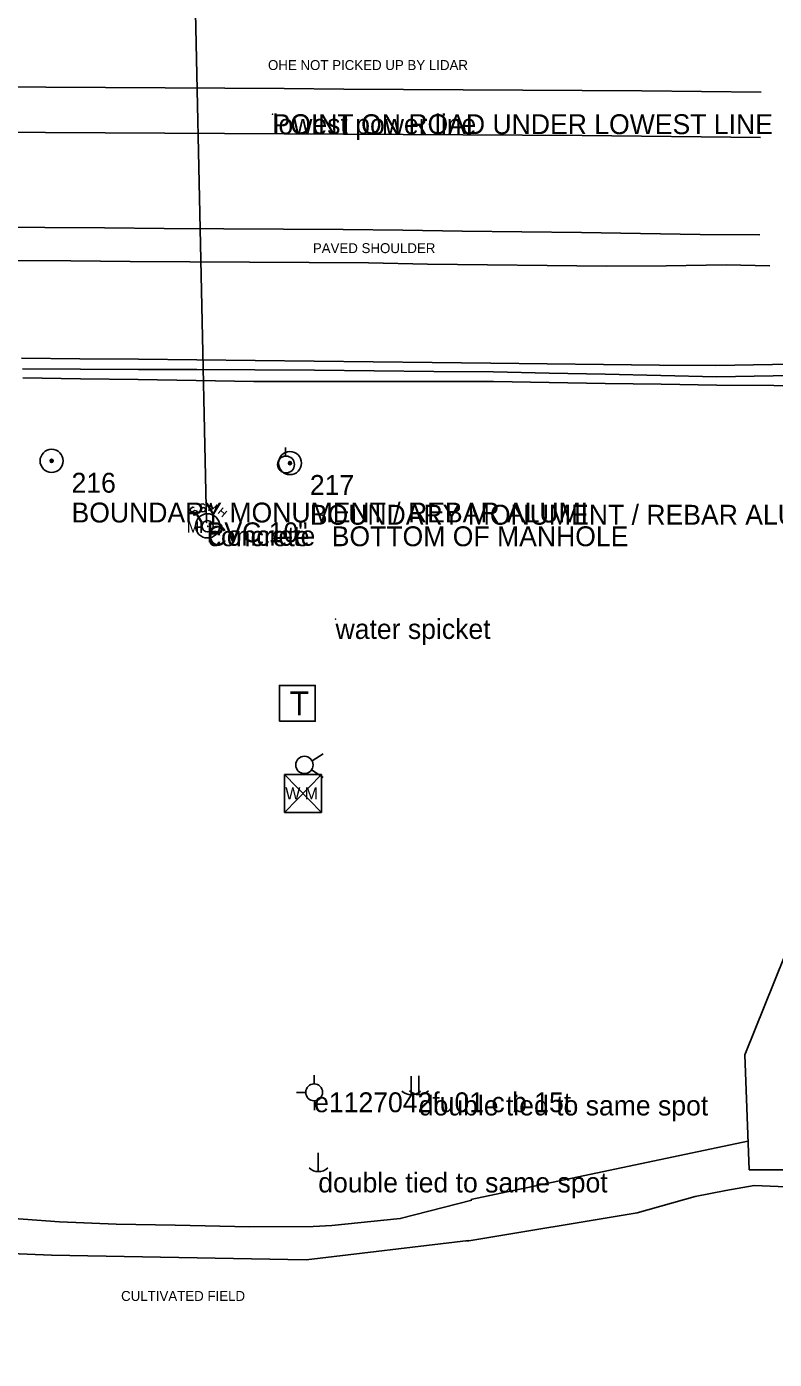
# Model space of a CAD drawing. Extents: x 1802180 to 1804859, y 572524 to 575172.
# Drawn here: x 1804394.4 to 1804582.6, y 573491.7 to 573826.9 of the extents above; entities that cross this region are included whole.
import ezdxf

# ---------------------------------------------------------------- set-up
doc = ezdxf.new("R2010")
doc.units = 0
for name, color, linetype in [('EX_EDGE_PAVEMENT', 7, 'Continuous'), ('EX_SHOULDER', 7, 'Continuous'), ('S_DITCHLINE', 7, 'Continuous'), ('S_ELECTRIC_UTILITIES_ANNOT', 7, 'Continuous'), ('S_IRON_PIN', 7, 'Continuous'), ('S_IRON_PIN_ANNOT', 7, 'Continuous'), ('S_MANHOLE', 7, 'Continuous'), ('S_MANHOLE_ANNOT', 7, 'Continuous'), ('S_MISC_BOUNDARY', 7, 'Continuous'), ('S_MISC_BOUNDARY_ANNOT', 7, 'Continuous'), ('S_MSC_PT_SYM', 7, 'Continuous'), ('S_PARKING', 7, 'Continuous'), ('S_PAVEMENT_CROWN', 7, 'Continuous'), ('S_SANITARY_SEWER', 7, 'Continuous'), ('S_SANITARY_SEWER_ANNOT', 7, 'Continuous'), ('S_SHOULDER_ANNOT', 7, 'Continuous'), ('S_SURVEY_TEXT', 7, 'Continuous'), ('S_SURVEY_TEXT_ANNOT', 7, 'Continuous'), ('S_TELEPHONE_UTILITIES', 7, 'Continuous'), ('S_TRAILS', 7, 'Continuous'), ('S_UTILITY_POLE', 7, 'Continuous'), ('S_UTILITY_POLE_ANNOT', 7, 'Continuous'), ('S_UTL_PT_SYM', 7, 'Continuous'), ('S_WATER_UTILITIES', 7, 'Continuous')]:
    doc.layers.add(name, color=color, linetype=linetype)

msp = doc.modelspace()

# ---------------------------------------------------------------- linework, layer by layer
at = {"layer": 'EX_EDGE_PAVEMENT'}
msp.add_lwpolyline([(1804578.95, 573774.58), (1804563.95, 573774.68), (1804548.95, 573774.89), (1804534.07, 573775.15), (1804519.07, 573775.33), (1804504.07, 573775.48), (1804489.08, 573775.71), (1804474.08, 573775.95), (1804459.08, 573776.02), (1804444.08, 573776.08), (1804429.05, 573776.18), (1804414.05, 573776.29), (1804399.05, 573776.4), (1804384.14, 573776.49)], dxfattribs=at)
at = {"layer": 'EX_SHOULDER'}
msp.add_lwpolyline([(1804270.56, 573769.08), (1804285.47, 573768.95), (1804300.47, 573768.69), (1804315.5, 573768.52), (1804330.52, 573768.41), (1804345.52, 573768.3), (1804360.53, 573768.22), (1804375.55, 573768.19), (1804390.52, 573768.1), (1804405.52, 573768), (1804420.51, 573767.89), (1804435.52, 573767.78), (1804450.52, 573767.69), (1804465.55, 573767.65), (1804480.52, 573767.56), (1804495.37, 573767.21), (1804510.47, 573767.06), (1804525.47, 573766.88), (1804540.38, 573766.7), (1804555.38, 573766.8), (1804570.51, 573767.04), (1804581.48, 573766.76)], dxfattribs=at)
at = {"layer": 'S_DITCHLINE'}
for points in [[(1804393.16, 573743.54), (1804407.86, 573743.4), (1804422.57, 573743.25), (1804437.28, 573743.1), (1804451.98, 573742.96), (1804466.81, 573742.8), (1804481.64, 573742.64), (1804496.47, 573742.48), (1804511.3, 573742.32), (1804525.45, 573742.15), (1804539.61, 573741.99), (1804553.76, 573741.82), (1804567.92, 573741.66), (1804582.19, 573741.99), (1804596.45, 573742.33)], [(1804393.35, 573740.82), (1804407.98, 573740.78), (1804422.6, 573740.73), (1804437.23, 573740.69), (1804451.85, 573740.65), (1804466.88, 573740.51), (1804481.9, 573740.37), (1804496.93, 573740.23), (1804511.95, 573740.1), (1804525.98, 573739.79), (1804540.02, 573739.49), (1804554.05, 573739.18), (1804568.08, 573738.88), (1804582.3, 573739.13), (1804596.52, 573739.38)], [(1804393.44, 573738.62), (1804407.99, 573738.38), (1804422.54, 573738.15), (1804437.08, 573737.91), (1804451.63, 573737.68), (1804466.7, 573737.67), (1804481.77, 573737.66), (1804496.84, 573737.65), (1804511.91, 573737.64), (1804525.98, 573737.41), (1804540.05, 573737.19), (1804554.11, 573736.97), (1804568.18, 573736.75), (1804582.53, 573736.68), (1804596.88, 573736.62)]]:
    msp.add_lwpolyline(points, dxfattribs=at)
at = {"layer": 'S_IRON_PIN'}
for centre, radius in [((1804400.73, 573717.71), 2.91), ((1804400.73, 573717.71), 0.411), ((1804400.73, 573717.71), 0.262), ((1804400.73, 573717.71), 0.212), ((1804400.73, 573717.71), 0.145), ((1804400.73, 573717.71), 0.0822), ((1804400.73, 573717.71), 0.0581), ((1804460.72, 573717.15), 2.91), ((1804460.72, 573717.15), 0.411), ((1804460.72, 573717.15), 0.262), ((1804460.72, 573717.15), 0.212), ((1804460.72, 573717.15), 0.145), ((1804460.72, 573717.15), 0.0822), ((1804460.72, 573717.15), 0.0581)]:
    msp.add_circle(centre, radius, dxfattribs=at)
at = {"layer": 'S_MANHOLE'}
for p, q in [((1804436.82, 573701.04), (1804438.4, 573701.04)), ((1804438.4, 573699.63), (1804438.4, 573702.47))]:
    msp.add_line(p, q, dxfattribs=at)
msp.add_circle((1804439.99, 573701.25), 1.42, dxfattribs=at)
at = {"layer": 'S_MISC_BOUNDARY'}
for points in [[(1804505.21, 573521.43), (1804548.12, 573528.55), (1804562.67, 573532.64), (1804570.46, 573534.2), (1804577.56, 573535.38), (1804635.95, 573532.96), (1804699.73, 573530.94), (1804713.49, 573529.95), (1804733.85, 573526.62), (1804745.57, 573524.69), (1804765.3, 573523.78), (1804783.44, 573521.61), (1804800.81, 573520.18), (1804809.98, 573519.87), (1804816.92, 573516.85), (1804820.25, 573513.61), (1804821.85, 573510.93)], [(1804339.86, 573491.68), (1804339.25, 573520.41), (1804400.7, 573517.93), (1804464.79, 573516.71), (1804505.61, 573521.55)]]:
    msp.add_lwpolyline(points, dxfattribs=at)
at = {"layer": 'S_MSC_PT_SYM'}
for points in [[(1804456.33, 573804.9), (1804456.33, 573804.95), (1804456.33, 573804.9), (1804456.28, 573804.9), (1804456.33, 573804.9), (1804456.33, 573804.85), (1804456.33, 573804.9), (1804456.38, 573804.9)], [(1804472.19, 573677.91), (1804472.19, 573677.96), (1804472.19, 573677.91), (1804472.14, 573677.91), (1804472.19, 573677.91), (1804472.19, 573677.86), (1804472.19, 573677.91), (1804472.24, 573677.91)]]:
    msp.add_lwpolyline(points, dxfattribs=at)
at = {"layer": 'S_PARKING'}
msp.add_lwpolyline([(1804786.88, 573526.83), (1804786.88, 573526.83), (1804744.65, 573531.49), (1804677.97, 573539.39), (1804576.31, 573539.38), (1804575.23, 573568.33), (1804600.03, 573629.91), (1804655.49, 573715.42)], dxfattribs=at)
at = {"layer": 'S_PAVEMENT_CROWN'}
for points in [[(1804579.29, 573810.48), (1804564.29, 573810.62), (1804549.29, 573810.76), (1804534.29, 573810.88), (1804519.29, 573810.97), (1804504.29, 573811.06), (1804489.29, 573811.15), (1804474.29, 573811.25), (1804459.29, 573811.34), (1804444.29, 573811.43), (1804429.29, 573811.52), (1804414.29, 573811.62), (1804399.29, 573811.73), (1804384.29, 573811.82)], [(1804384.24, 573800.44), (1804399.21, 573800.35), (1804414.21, 573800.24), (1804429.21, 573800.13), (1804444.22, 573800.04), (1804459.22, 573799.97), (1804474.22, 573799.9), (1804489.22, 573799.81), (1804504.22, 573799.71), (1804519.22, 573799.61), (1804534.22, 573799.52), (1804549.18, 573799.38), (1804564.18, 573799.22), (1804579.18, 573799.02)]]:
    msp.add_lwpolyline(points, dxfattribs=at)
at = {"layer": 'S_SANITARY_SEWER'}
for p, q in [((1804439.74, 573702.23), (1804435.17, 573908.88)), ((1804435.64, 573705.67), (1804435.56, 573705.28)), ((1804435.56, 573705.28), (1804435.76, 573705.01)), ((1804436.18, 573706.05), (1804435.64, 573705.67)), ((1804435.76, 573705.01), (1804436.18, 573704.89)), ((1804436.61, 573705.98), (1804436.18, 573706.05)), ((1804436.18, 573704.89), (1804436.73, 573705.24)), ((1804436.73, 573705.24), (1804437.19, 573705.16)), ((1804437.27, 573704.46), (1804436.73, 573704.08)), ((1804437.19, 573705.16), (1804437.35, 573704.89)), ((1804437.35, 573704.89), (1804437.27, 573704.46)), ((1804442.62, 573704.43), (1804443.86, 573705.9)), ((1804443.28, 573705.2), (1804444.24, 573704.39)), ((1804444.83, 573705.08), (1804443.59, 573703.61)), ((1804436.73, 573704.08), (1804436.34, 573704.15))]:
    msp.add_line(p, q, dxfattribs=at)
for points in [[(1804439.28, 573706.6), (1804438.94, 573706.87), (1804438.28, 573706.79), (1804438.04, 573706.44), (1804438.08, 573706.13), (1804438.43, 573705.82), (1804439.05, 573705.94), (1804439.44, 573705.63), (1804439.48, 573705.32), (1804439.21, 573704.93), (1804438.59, 573704.85), (1804438.24, 573705.12)], [(1804441.73, 573704.74), (1804442.27, 573706.6), (1804441.22, 573705.59), (1804440.83, 573707.02), (1804440.29, 573705.16)]]:
    msp.add_lwpolyline(points, dxfattribs=at)
msp.add_circle((1804439.97, 573701.36), 3.05, dxfattribs=at)
at = {"layer": 'S_SURVEY_TEXT'}
msp.add_line((1804455.18, 573818.53), (1804455.18, 573818.53), dxfattribs=at)
at = {"layer": 'S_TELEPHONE_UTILITIES'}
msp.add_lwpolyline([(1804458.06, 573652.21), (1804458.06, 573661.21), (1804467.06, 573661.21), (1804467.06, 573652.21)], close=True, dxfattribs=at)
at = {"layer": 'S_TRAILS'}
msp.add_line((1804506.23, 573531.88), (1804575.96, 573546.6), dxfattribs=at)
msp.add_lwpolyline([(1804237.78, 573515.53), (1804237.78, 573515.53), (1804256.03, 573517.74), (1804309, 573528.42), (1804314.65, 573530.34), (1804320.9, 573530.65), (1804330.17, 573530.55), (1804346.23, 573530.21), (1804362.73, 573528.81), (1804384.35, 573527.65), (1804402.68, 573526.31), (1804416.97, 573525.69), (1804431.84, 573525.41), (1804450.6, 573524.99), (1804466.55, 573525.14), (1804471.29, 573525.33), (1804488.47, 573527.11), (1804506.5, 573531.75)], dxfattribs=at)
at = {"layer": 'S_UTILITY_POLE'}
for p, q in [((1804459.6, 573718.93), (1804459.6, 573721.03)), ((1804466.8, 573560.96), (1804466.8, 573563.21)), ((1804491.19, 573562.95), (1804491.19, 573558.22)), ((1804493.12, 573562.99), (1804493.12, 573558.26)), ((1804464.71, 573558.83), (1804462.38, 573558.83)), ((1804466.88, 573554.41), (1804466.88, 573556.74)), ((1804467.81, 573543.61), (1804467.81, 573538.89))]:
    msp.add_line(p, q, dxfattribs=at)
for centre in [(1804459.72, 573716.79), (1804466.8, 573558.85)]:
    msp.add_circle(centre, 2.13, dxfattribs=at)
for centre in [(1804491.25, 573561.64), (1804493.19, 573561.68), (1804467.88, 573542.31)]:
    msp.add_arc(centre, 3.41, 226.3972, 313.6028, dxfattribs=at)
at = {"layer": 'S_UTL_PT_SYM'}
for points in [[(1804456.33, 573804.9), (1804456.33, 573804.95), (1804456.33, 573804.9), (1804456.28, 573804.9), (1804456.33, 573804.9), (1804456.33, 573804.85), (1804456.33, 573804.9), (1804456.38, 573804.9)], [(1804439.74, 573702.23), (1804439.74, 573702.28), (1804439.74, 573702.23), (1804439.69, 573702.23), (1804439.74, 573702.23), (1804439.74, 573702.18), (1804439.74, 573702.23), (1804439.79, 573702.23)], [(1804440.01, 573701.24), (1804440.01, 573701.29), (1804440.01, 573701.24), (1804439.96, 573701.24), (1804440.01, 573701.24), (1804440.01, 573701.19), (1804440.01, 573701.24), (1804440.06, 573701.24)]]:
    msp.add_lwpolyline(points, dxfattribs=at)
at = {"layer": 'S_WATER_UTILITIES'}
for p, q in [((1804466.26, 573642.26), (1804469.08, 573643.99)), ((1804459.33, 573638.77), (1804468.67, 573638.77)), ((1804459.33, 573638.77), (1804459.33, 573629.28)), ((1804459.33, 573638.77), (1804468.67, 573629.28)), ((1804468.67, 573638.77), (1804459.33, 573629.28)), ((1804466.14, 573639.95), (1804469.05, 573638.03)), ((1804468.67, 573638.77), (1804468.67, 573629.28)), ((1804459.33, 573629.28), (1804468.67, 573629.28))]:
    msp.add_line(p, q, dxfattribs=at)
msp.add_circle((1804464.36, 573641.21), 2.18, dxfattribs=at)

# ---------------------------------------------------------------- texts
at = {"layer": 'S_ELECTRIC_UTILITIES_ANNOT'}
msp.add_text('lowest power line ', height=5, dxfattribs=at).set_placement((1804456.33, 573799.9))
at = {"layer": 'S_IRON_PIN_ANNOT'}
for s, p in [('216', (1804405.73, 573709.71)), ('217', (1804465.72, 573709.15)), ('BOUNDARY MONUMENT / REBAR ALUMI ', (1804405.73, 573702.21)), ('BOUNDARY MONUMENT / REBAR ALUMI ', (1804465.72, 573701.65))]:
    msp.add_text(s, height=5, dxfattribs=at).set_placement(p)
at = {"layer": 'S_MANHOLE'}
msp.add_text('M', height=2.82, dxfattribs=at).set_placement((1804434.74, 573699.67))
at = {"layer": 'S_MANHOLE_ANNOT'}
msp.add_text('concrete   BOTTOM OF MANHOLE', height=5, dxfattribs=at).set_placement((1804440.01, 573696.24))
at = {"layer": 'S_MISC_BOUNDARY_ANNOT'}
msp.add_text('CULTIVATED FIELD', height=2.5, dxfattribs=at).set_placement((1804418.21, 573506.38))
at = {"layer": 'S_SANITARY_SEWER_ANNOT'}
for s, p in [('PVC 10" ', (1804439.74, 573697.23)), ('Concrete', (1804439.97, 573696.36))]:
    msp.add_text(s, height=5, dxfattribs=at).set_placement(p)
at = {"layer": 'S_SHOULDER_ANNOT'}
msp.add_text('PAVED SHOULDER', height=2.5, dxfattribs=at).set_placement((1804466.47, 573769.97))
at = {"layer": 'S_SURVEY_TEXT_ANNOT'}
for s, height, p in [('OHE NOT PICKED UP BY LIDAR', 2.5, (1804455.18, 573816.03)), ('POINT ON ROAD UNDER LOWEST LINE ', 5, (1804456.33, 573799.9)), ('water spicket', 5, (1804472.19, 573672.91))]:
    msp.add_text(s, height=height, dxfattribs=at).set_placement(p)
at = {"layer": 'S_TELEPHONE_UTILITIES'}
msp.add_text('T', height=6, rotation=360, dxfattribs=at).set_placement((1804460.62, 573653.71))
at = {"layer": 'S_UTILITY_POLE_ANNOT'}
for s, p in [('e1127042fu01 c b 15t', (1804466.8, 573553.85)), ('double tied to same spot', (1804493.14, 573553.04)), ('double tied to same spot', (1804467.83, 573533.67))]:
    msp.add_text(s, height=5, dxfattribs=at).set_placement(p)
at = {"layer": 'S_WATER_UTILITIES'}
msp.add_text('W M', height=3, rotation=360, dxfattribs=at).set_placement((1804459.54, 573632.54))

doc.saveas('drawing.dxf')
